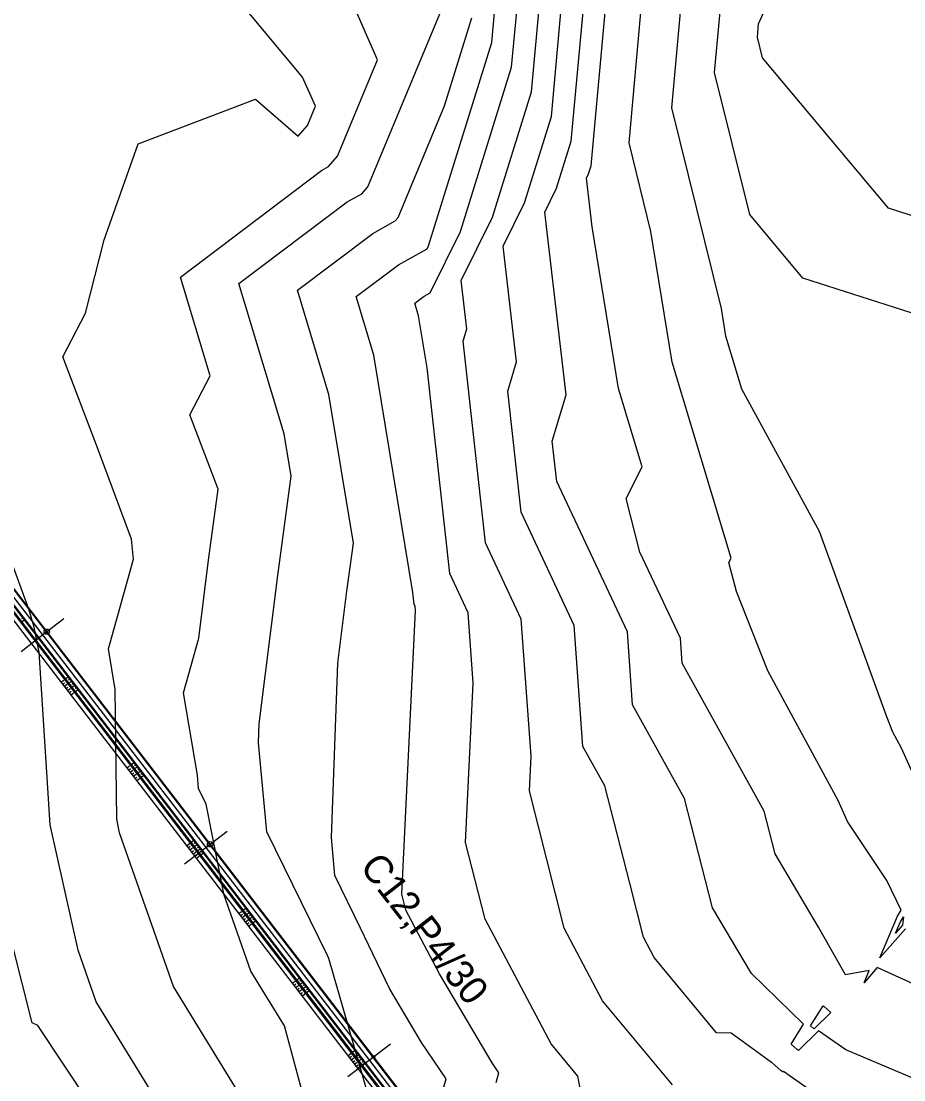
# Model space of a CAD drawing. Extents: x -549238 to -546764, y -1036895 to -1033794.
# Drawn here: x -548407.8 to -548078.5, y -1034975.5 to -1034580.6 of the extents above; entities that cross this region are included whole.
import ezdxf

# ---------------------------------------------------------------- set-up
doc = ezdxf.new("R2010")
doc.units = 0
for name, color, linetype in [('hlavni_vrst', 7, 'Continuous'), ('norm_vrst', 7, 'Continuous'), ('u_prikop_C12', 7, 'Continuous'), ('u_sirka_0_5m', 7, 'Continuous'), ('u_sirka_1_0m', 7, 'Continuous'), ('x_navrh_C12', 7, 'Continuous'), ('x_osa_C12', 7, 'Continuous'), ('x_popis_pricne_rezy_C12', 7, 'Continuous'), ('x_popis_velky_C12', 7, 'Continuous')]:
    doc.layers.add(name, color=color, linetype=linetype)

msp = doc.modelspace()

# ---------------------------------------------------------------- linework, layer by layer
at = {"layer": 'hlavni_vrst'}
for p, q in [((-548181.01, -1034626.04), (-548172.84, -1034534.63)), ((-548224.81, -1034597.75), (-548220.73, -1034553.48)), ((-548302.78, -1034601.44), (-548341.67, -1034554.86)), ((-548243.89, -1034659.08), (-548224.81, -1034597.75)), ((-548298.02, -1034612.3), (-548302.78, -1034601.44)), ((-548364.17, -1034626.36), (-548320.4, -1034609.68)), ((-548320.4, -1034609.68), (-548304.49, -1034623.49)), ((-548301, -1034619.47), (-548298.02, -1034612.3)), ((-548304.49, -1034623.49), (-548301, -1034619.47)), ((-548376.8, -1034662.17), (-548364.17, -1034626.36)), ((-548172.85, -1034659.09), (-548181.01, -1034626.04)), ((-548255.14, -1034681.89), (-548243.89, -1034659.08)), ((-548164.9, -1034707.86), (-548172.85, -1034659.09)), ((-548383.78, -1034689.57), (-548376.8, -1034662.17)), ((-548260.92, -1034685.79), (-548257.48, -1034683.19)), ((-548257.48, -1034683.19), (-548255.14, -1034681.89)), ((-548259.49, -1034690.57), (-548260.92, -1034685.79)), ((-548392.2, -1034705.88), (-548383.78, -1034689.57)), ((-548256.29, -1034709.94), (-548259.49, -1034690.57)), ((-548379.35, -1034739.81), (-548392.2, -1034705.88)), ((-548142.85, -1034780.89), (-548164.9, -1034707.86)), ((-548247.86, -1034786.65), (-548256.29, -1034709.94)), ((-548366.57, -1034773.82), (-548379.35, -1034739.81)), ((-548365.91, -1034781.32), (-548366.57, -1034773.82)), ((-548375.22, -1034814.79), (-548365.91, -1034781.32)), ((-548143.73, -1034782.59), (-548142.85, -1034780.89)), ((-548140.96, -1034793.3), (-548143.73, -1034782.59)), ((-548240.98, -1034801.29), (-548247.86, -1034786.65)), ((-548129.19, -1034823), (-548140.96, -1034793.3)), ((-548239.11, -1034827.58), (-548240.98, -1034801.29)), ((-548372.7, -1034829.89), (-548375.22, -1034814.79)), ((-548102.99, -1034871.31), (-548129.19, -1034823)), ((-548372.03, -1034878.25), (-548372.7, -1034829.89)), ((-548241.98, -1034887.04), (-548239.11, -1034827.58)), ((-548099.52, -1034879.12), (-548102.99, -1034871.31)), ((-548371.03, -1034883.34), (-548372.03, -1034878.25)), ((-548084.87, -1034901.12), (-548099.52, -1034879.12)), ((-548350.92, -1034940.67), (-548371.03, -1034883.34)), ((-548234.71, -1034915.58), (-548241.98, -1034887.04)), ((-548079.44, -1034912.17), (-548084.87, -1034901.12)), ((-548080.86, -1034914.52), (-548079.44, -1034912.17)), ((-548210.1, -1034962.11), (-548234.71, -1034915.58)), ((-548087.44, -1034930.05), (-548080.86, -1034914.52)), ((-548077.94, -1034919.17), (-548087.44, -1034930.05)), ((-548325.66, -1034981.81), (-548350.92, -1034940.67)), ((-548200.15, -1034974.14), (-548210.1, -1034962.11)), ((-548198.58, -1034982.16), (-548200.15, -1034974.14))]:
    msp.add_line(p, q, dxfattribs=at)
at = {"layer": 'norm_vrst'}
for p, q in [((-548195.18, -1034634.51), (-548185.07, -1034524.89)), ((-548202.58, -1034625.32), (-548193.98, -1034532.04)), ((-548274.82, -1034595.07), (-548298.64, -1034540.76)), ((-548209.99, -1034616.13), (-548202.9, -1034539.18)), ((-548217.4, -1034606.94), (-548211.81, -1034546.33)), ((-548165.04, -1034612.88), (-548159.45, -1034550.3)), ((-548232.22, -1034588.56), (-548229.64, -1034560.63)), ((-548149.08, -1034599.71), (-548146.06, -1034565.97)), ((-548278.43, -1034642.39), (-548251.62, -1034577.85)), ((-548132.68, -1034581.65), (-548129.58, -1034574.7)), ((-548249.83, -1034612.15), (-548239.63, -1034579.37)), ((-548133.11, -1034586.55), (-548132.68, -1034581.65)), ((-548255.83, -1034664.46), (-548232.22, -1034588.56)), ((-548131.21, -1034594.26), (-548133.11, -1034586.55)), ((-548289.72, -1034630.93), (-548274.82, -1034595.07)), ((-548084.19, -1034650.32), (-548131.21, -1034594.26)), ((-548135.97, -1034652.77), (-548149.08, -1034599.71)), ((-548231.95, -1034653.7), (-548217.4, -1034606.94)), ((-548267.15, -1034653.85), (-548249.83, -1034612.15)), ((-548146.55, -1034687.75), (-548165.04, -1034612.88)), ((-548220.01, -1034648.33), (-548209.99, -1034616.13)), ((-548208.07, -1034642.95), (-548202.58, -1034625.32)), ((-548293.11, -1034634.84), (-548289.72, -1034630.93)), ((-548348.38, -1034676.06), (-548295.78, -1034636.32)), ((-548295.78, -1034636.32), (-548293.11, -1034634.84)), ((-548196.13, -1034637.57), (-548195.18, -1034634.51)), ((-548196.89, -1034639.11), (-548196.13, -1034637.57)), ((-548194.75, -1034657.36), (-548196.89, -1034639.11)), ((-548286.2, -1034648.04), (-548280.68, -1034644.97)), ((-548280.68, -1034644.97), (-548278.43, -1034642.39)), ((-548212.46, -1034651.84), (-548208.07, -1034642.95)), ((-548326.51, -1034678.49), (-548286.2, -1034648.04)), ((-548228.02, -1034664.57), (-548220.01, -1034648.33)), ((-548204.47, -1034720.05), (-548212.46, -1034651.84)), ((-548116.13, -1034676.43), (-548135.97, -1034652.77)), ((-548072.27, -1034654.17), (-548084.19, -1034650.32)), ((-548276.63, -1034659.75), (-548268.24, -1034655.11)), ((-548268.24, -1034655.11), (-548267.15, -1034653.85)), ((-548243.59, -1034677.3), (-548231.95, -1034653.7)), ((-548304.65, -1034680.92), (-548276.63, -1034659.75)), ((-548184.93, -1034717.6), (-548194.75, -1034657.36)), ((-548256.37, -1034665.55), (-548255.83, -1034664.46)), ((-548222.97, -1034707.7), (-548228.02, -1034664.57)), ((-548267.05, -1034671.47), (-548256.37, -1034665.55)), ((-548282.79, -1034683.36), (-548267.05, -1034671.47)), ((-548337.32, -1034712.91), (-548348.38, -1034676.06)), ((-548034.09, -1034702.92), (-548116.13, -1034676.43)), ((-548309.7, -1034734.52), (-548326.51, -1034678.49)), ((-548241.48, -1034695.36), (-548243.59, -1034677.3)), ((-548292.97, -1034719.87), (-548304.65, -1034680.92)), ((-548276.23, -1034705.22), (-548282.79, -1034683.36)), ((-548144.86, -1034698.12), (-548146.55, -1034687.75)), ((-548242.85, -1034699.92), (-548241.48, -1034695.36)), ((-548234.57, -1034775.21), (-548242.85, -1034699.92)), ((-548138.9, -1034717.87), (-548144.86, -1034698.12)), ((-548261.63, -1034793.74), (-548276.23, -1034705.22)), ((-548226.24, -1034718.6), (-548222.97, -1034707.7)), ((-548344.83, -1034727.44), (-548337.32, -1034712.91)), ((-548283.82, -1034775.31), (-548292.97, -1034719.87)), ((-548221.28, -1034763.77), (-548226.24, -1034718.6)), ((-548209.64, -1034737.28), (-548204.47, -1034720.05)), ((-548176.09, -1034746.9), (-548184.93, -1034717.6)), ((-548109.97, -1034770.99), (-548138.9, -1034717.87)), ((-548334.33, -1034755.14), (-548344.83, -1034727.44)), ((-548307.09, -1034750.36), (-548309.7, -1034734.52)), ((-548207.99, -1034752.34), (-548209.64, -1034737.28)), ((-548182.14, -1034758.61), (-548176.09, -1034746.9)), ((-548312.05, -1034787.45), (-548307.09, -1034750.36)), ((-548337.87, -1034781.62), (-548334.33, -1034755.14)), ((-548181.64, -1034808.42), (-548207.99, -1034752.34)), ((-548176.94, -1034778.68), (-548182.14, -1034758.61)), ((-548201.42, -1034806.04), (-548221.28, -1034763.77)), ((-548084.86, -1034840.06), (-548109.97, -1034770.99)), ((-548286.22, -1034793.29), (-548283.82, -1034775.31)), ((-548221.2, -1034803.67), (-548234.57, -1034775.21)), ((-548161.86, -1034810.79), (-548176.94, -1034778.68)), ((-548404.86, -1034799.92), (-548412.05, -1034780.52)), ((-548341.52, -1034810.82), (-548337.87, -1034781.62)), ((-548318.96, -1034842.78), (-548312.05, -1034787.45)), ((-548289.58, -1034820.09), (-548286.22, -1034793.29)), ((-548261.15, -1034798.08), (-548261.63, -1034793.74)), ((-548260.76, -1034798.91), (-548261.15, -1034798.08)), ((-548260.66, -1034800.4), (-548260.76, -1034798.91)), ((-548402.9, -1034806.68), (-548404.86, -1034799.92)), ((-548265.76, -1034906.31), (-548260.66, -1034800.4)), ((-548401.05, -1034816.01), (-548402.9, -1034806.68)), ((-548217.57, -1034854.76), (-548221.2, -1034803.67)), ((-548198.21, -1034851.18), (-548201.42, -1034806.04)), ((-548347.17, -1034831.13), (-548341.52, -1034810.82)), ((-548179.7, -1034835.65), (-548181.64, -1034808.42)), ((-548161.19, -1034820.11), (-548161.86, -1034810.79)), ((-548396.99, -1034880.35), (-548401.05, -1034816.01)), ((-548292.05, -1034885.13), (-548289.58, -1034820.09)), ((-548130.56, -1034875.29), (-548161.19, -1034820.11)), ((-548342.03, -1034861.93), (-548347.17, -1034831.13)), ((-548160.33, -1034870.54), (-548179.7, -1034835.65)), ((-548082.56, -1034845.87), (-548084.86, -1034840.06)), ((-548319.23, -1034849.75), (-548318.96, -1034842.78)), ((-548079.34, -1034851.8), (-548082.56, -1034845.87)), ((-548316.17, -1034883.06), (-548319.23, -1034849.75)), ((-548190.1, -1034865.79), (-548198.21, -1034851.18)), ((-548066.23, -1034881.33), (-548079.34, -1034851.8)), ((-548218.2, -1034867.77), (-548217.57, -1034854.76)), ((-548341.58, -1034866.81), (-548342.03, -1034861.93)), ((-548180.76, -1034902.12), (-548190.1, -1034865.79)), ((-548338.72, -1034872.64), (-548341.58, -1034866.81)), ((-548205.16, -1034918.95), (-548218.2, -1034867.77)), ((-548332.02, -1034906.58), (-548338.72, -1034872.64)), ((-548149.83, -1034911.36), (-548160.33, -1034870.54)), ((-548126.46, -1034891.22), (-548130.56, -1034875.29)), ((-548386.51, -1034927.14), (-548396.99, -1034880.35)), ((-548293.55, -1034929.15), (-548316.17, -1034883.06)), ((-548290.75, -1034899.3), (-548292.05, -1034885.13)), ((-548110.29, -1034918.6), (-548126.46, -1034891.22)), ((-548281.13, -1034918.9), (-548290.75, -1034899.3)), ((-548175.6, -1034922.33), (-548180.76, -1034902.12)), ((-548322.07, -1034934.95), (-548332.02, -1034906.58)), ((-548264.26, -1034912.2), (-548265.76, -1034906.31)), ((-548251.67, -1034936.01), (-548264.26, -1034912.2)), ((-548135.34, -1034935.88), (-548149.83, -1034911.36)), ((-548081.56, -1034920.82), (-548079.78, -1034916.62)), ((-548079.78, -1034916.62), (-548078.6, -1034914.67)), ((-548078.6, -1034914.67), (-548078.99, -1034917.88)), ((-548270.4, -1034941.39), (-548281.13, -1034918.9)), ((-548190.85, -1034946.02), (-548205.16, -1034918.95)), ((-548100.2, -1034936.38), (-548110.29, -1034918.6)), ((-548078.99, -1034917.88), (-548081.56, -1034920.82)), ((-548403.71, -1034954.3), (-548411.2, -1034924.15)), ((-548171.59, -1034929.93), (-548175.6, -1034922.33)), ((-548379.76, -1034946.38), (-548386.51, -1034927.14)), ((-548292.99, -1034930.32), (-548293.55, -1034929.15)), ((-548278.35, -1034981.13), (-548292.99, -1034930.32)), ((-548148.41, -1034957.93), (-548171.59, -1034929.93)), ((-548309.57, -1034955.32), (-548322.07, -1034934.95)), ((-548232.06, -1034969.21), (-548251.67, -1034936.01)), ((-548115.98, -1034954.78), (-548135.34, -1034935.88)), ((-548091.42, -1034934.79), (-548100.2, -1034936.38)), ((-548088.41, -1034933.65), (-548093.32, -1034939.28)), ((-548093.32, -1034939.28), (-548091.42, -1034934.79)), ((-548066.5, -1034943.54), (-548088.41, -1034933.65)), ((-548258.44, -1034961.64), (-548270.4, -1034941.39)), ((-548341.75, -1035008.31), (-548379.76, -1034946.38)), ((-548164.85, -1034977.44), (-548190.85, -1034946.02)), ((-548113.27, -1034955.43), (-548108.63, -1034947.86)), ((-548108.63, -1034947.86), (-548108.21, -1034948.2)), ((-548108.21, -1034948.2), (-548105.77, -1034950.4)), ((-548105.77, -1034950.4), (-548112, -1034956.5)), ((-548401.52, -1034955.28), (-548403.71, -1034954.3)), ((-548367.9, -1035005.68), (-548401.52, -1034955.28)), ((-548297.51, -1035000.24), (-548309.57, -1034955.32)), ((-548120.5, -1034962.22), (-548115.91, -1034954.73)), ((-548115.91, -1034954.73), (-548115.98, -1034954.78)), ((-548112.22, -1034956.37), (-548113.27, -1034955.43)), ((-548112, -1034956.5), (-548112.22, -1034956.37)), ((-548142.91, -1034958.09), (-548148.41, -1034957.93)), ((-548127.88, -1034969.1), (-548142.91, -1034958.09)), ((-548110.32, -1034957.28), (-548117.74, -1034964.56)), ((-548100.16, -1034964.38), (-548110.32, -1034957.28)), ((-548249.2, -1034975.11), (-548258.44, -1034961.64)), ((-548118.22, -1034964.27), (-548120.5, -1034962.22)), ((-548117.74, -1034964.56), (-548118.22, -1034964.27)), ((-548058.63, -1034981.96), (-548100.16, -1034964.38)), ((-548127.69, -1034968.94), (-548127.88, -1034969.1)), ((-548127.74, -1034969.01), (-548127.69, -1034968.94)), ((-548124.22, -1034972.17), (-548127.74, -1034969.01)), ((-548229.52, -1034972.92), (-548232.06, -1034969.21)), ((-548230.55, -1034976.55), (-548229.52, -1034972.92)), ((-548127.88, -1034969.1), (-548127.88, -1034969.1)), ((-548127.88, -1034969.1), (-548127.88, -1034969.1)), ((-548127.88, -1034969.1), (-548127.88, -1034969.1)), ((-548124.22, -1034972.17), (-548124.22, -1034972.17)), ((-548124.22, -1034972.17), (-548124.22, -1034972.17)), ((-548124.22, -1034972.17), (-548124.22, -1034972.17)), ((-548123.48, -1034972.61), (-548124.22, -1034972.17)), ((-548123.33, -1034972.47), (-548123.48, -1034972.61)), ((-548088.99, -1034996.46), (-548123.33, -1034972.47)), ((-548250.47, -1034979.54), (-548249.2, -1034975.11))]:
    msp.add_line(p, q, dxfattribs=at)
at = {"layer": 'u_prikop_C12'}
for p, q in [((-548734.21, -1034380.33), (-548250.98, -1035009.26)), ((-548733.99, -1034379.97), (-548250.64, -1035009.01)), ((-548732.7, -1034385.01), (-548251.32, -1035011.54)), ((-548407.18, -1034803.26), (-548407.62, -1034803.59)), ((-548406.57, -1034804.05), (-548407.33, -1034804.63)), ((-548392.94, -1034827.21), (-548391.88, -1034826.39)), ((-548390.26, -1034825.28), (-548391.01, -1034825.86)), ((-548389.65, -1034826.08), (-548390.07, -1034826.4)), ((-548389.04, -1034826.87), (-548389.8, -1034827.45)), ((-548392.33, -1034828), (-548391.57, -1034827.41)), ((-548391.72, -1034828.8), (-548390.66, -1034827.98)), ((-548391.11, -1034829.59), (-548390.35, -1034829)), ((-548390.51, -1034830.38), (-548389.43, -1034829.56)), ((-548389.9, -1034831.17), (-548389.14, -1034830.59)), ((-548388.43, -1034827.66), (-548388.86, -1034827.99)), ((-548387.82, -1034828.45), (-548388.58, -1034829.03)), ((-548387.21, -1034829.25), (-548387.65, -1034829.58)), ((-548386.61, -1034830.04), (-548387.36, -1034830.62)), ((-548389.29, -1034831.97), (-548388.21, -1034831.14)), ((-548368.37, -1034859.19), (-548367.31, -1034858.37)), ((-548365.69, -1034857.26), (-548366.44, -1034857.84)), ((-548365.08, -1034858.06), (-548365.5, -1034858.38)), ((-548367.76, -1034859.98), (-548367, -1034859.39)), ((-548367.15, -1034860.77), (-548366.09, -1034859.96)), ((-548366.54, -1034861.57), (-548365.78, -1034860.98)), ((-548365.93, -1034862.36), (-548364.86, -1034861.54)), ((-548364.47, -1034858.85), (-548365.23, -1034859.43)), ((-548363.86, -1034859.64), (-548364.29, -1034859.97)), ((-548363.25, -1034860.43), (-548364.01, -1034861.01)), ((-548362.64, -1034861.23), (-548363.08, -1034861.56)), ((-548362.03, -1034862.02), (-548362.79, -1034862.6)), ((-548365.33, -1034863.15), (-548364.57, -1034862.57)), ((-548364.72, -1034863.95), (-548363.64, -1034863.12)), ((-548346.09, -1034888.18), (-548345.03, -1034887.37)), ((-548345.49, -1034888.97), (-548344.72, -1034888.39)), ((-548344.88, -1034889.77), (-548343.81, -1034888.95)), ((-548344.27, -1034890.56), (-548343.51, -1034889.98)), ((-548343.41, -1034886.26), (-548344.17, -1034886.84)), ((-548342.8, -1034887.05), (-548343.22, -1034887.37)), ((-548342.19, -1034887.84), (-548342.95, -1034888.42)), ((-548341.59, -1034888.63), (-548342.01, -1034888.96)), ((-548340.98, -1034889.43), (-548341.73, -1034890.01)), ((-548343.66, -1034891.35), (-548342.59, -1034890.53)), ((-548343.05, -1034892.15), (-548342.29, -1034891.56)), ((-548342.44, -1034892.94), (-548341.36, -1034892.11)), ((-548340.37, -1034890.22), (-548340.8, -1034890.55)), ((-548339.76, -1034891.01), (-548340.51, -1034891.59)), ((-548326.64, -1034913.51), (-548325.58, -1034912.69)), ((-548326.03, -1034914.3), (-548325.26, -1034913.71)), ((-548323.96, -1034911.58), (-548324.71, -1034912.16)), ((-548323.35, -1034912.37), (-548323.76, -1034912.69)), ((-548322.74, -1034913.17), (-548323.49, -1034913.75)), ((-548325.42, -1034915.09), (-548324.35, -1034914.27)), ((-548324.81, -1034915.89), (-548324.05, -1034915.3)), ((-548324.2, -1034916.68), (-548323.13, -1034915.86)), ((-548323.59, -1034917.47), (-548322.83, -1034916.89)), ((-548322.98, -1034918.26), (-548321.91, -1034917.44)), ((-548322.13, -1034913.96), (-548322.55, -1034914.29)), ((-548321.52, -1034914.75), (-548322.27, -1034915.33)), ((-548320.91, -1034915.55), (-548321.34, -1034915.88)), ((-548320.3, -1034916.34), (-548321.05, -1034916.92)), ((-548306.65, -1034939.52), (-548305.59, -1034938.7)), ((-548306.04, -1034940.31), (-548305.28, -1034939.73)), ((-548305.43, -1034941.11), (-548304.37, -1034940.29)), ((-548304.82, -1034941.9), (-548304.06, -1034941.31)), ((-548303.97, -1034937.59), (-548304.72, -1034938.17)), ((-548303.36, -1034938.39), (-548303.78, -1034938.71)), ((-548302.75, -1034939.18), (-548303.5, -1034939.76)), ((-548302.14, -1034939.97), (-548302.57, -1034940.3)), ((-548301.53, -1034940.77), (-548302.29, -1034941.34)), ((-548304.21, -1034942.69), (-548303.14, -1034941.87)), ((-548303.6, -1034943.48), (-548302.85, -1034942.9)), ((-548302.99, -1034944.28), (-548301.92, -1034943.45)), ((-548300.92, -1034941.56), (-548301.36, -1034941.89)), ((-548300.31, -1034942.35), (-548301.07, -1034942.93)), ((-548283.22, -1034964.6), (-548283.98, -1034965.18)), ((-548285.9, -1034966.52), (-548284.84, -1034965.71)), ((-548285.29, -1034967.32), (-548284.53, -1034966.73)), ((-548284.68, -1034968.11), (-548283.62, -1034967.29)), ((-548284.08, -1034968.9), (-548283.31, -1034968.32)), ((-548283.47, -1034969.69), (-548282.39, -1034968.87)), ((-548282.61, -1034965.39), (-548283.03, -1034965.71)), ((-548282, -1034966.18), (-548282.76, -1034966.76)), ((-548281.39, -1034966.98), (-548281.82, -1034967.3)), ((-548280.78, -1034967.77), (-548281.54, -1034968.35)), ((-548280.17, -1034968.56), (-548280.61, -1034968.89)), ((-548282.86, -1034970.49), (-548282.1, -1034969.9)), ((-548282.25, -1034971.28), (-548281.17, -1034970.45)), ((-548279.57, -1034969.35), (-548280.32, -1034969.93))]:
    msp.add_line(p, q, dxfattribs=at)
at = {"layer": 'u_sirka_0_5m'}
msp.add_circle((-548276.36, -1034966.96), 0.5, dxfattribs=at)
at = {"layer": 'u_sirka_1_0m'}
for centre in [(-548398.21, -1034808.37), (-548337.29, -1034887.66)]:
    msp.add_circle(centre, 1, dxfattribs=at)
at = {"layer": 'x_navrh_C12'}
for p, q in [((-548741.44, -1034362.06), (-548233.23, -1035023.51)), ((-548743.07, -1034365.69), (-548236, -1035025.64)), ((-548732.04, -1034380.45), (-548236.2, -1035025.8)), ((-548414.25, -1034787.5), (-548233.03, -1035023.36))]:
    msp.add_line(p, q, dxfattribs=at)
at = {"layer": 'x_osa_C12'}
msp.add_lwpolyline([(-548743.02, -1034362.88), (-548206.06, -1035061.74)], dxfattribs=at)
at = {"layer": 'x_popis_pricne_rezy_C12'}
for points in [[(-548407.73, -1034815.68), (-548399.8, -1034809.58), (-548391.87, -1034803.49)], [(-548346.8, -1034894.97), (-548338.87, -1034888.88), (-548330.94, -1034882.79)], [(-548285.88, -1034974.27), (-548277.95, -1034968.18), (-548270.02, -1034962.09)]]:
    msp.add_lwpolyline(points, dxfattribs=at)

# ---------------------------------------------------------------- texts
at = {"layer": 'x_popis_velky_C12'}
msp.add_text('C12,P4/30', height=10.5, rotation=307.9526, dxfattribs=at).set_placement((-548281.77, -1034896.13))

doc.saveas('drawing.dxf')
